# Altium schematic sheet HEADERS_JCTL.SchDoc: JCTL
size A3; Author: Silvio Navaretti; CompanyName: ARDUINO; DrawnBy: Silvio Navaretti; Engineer: Silvio Navaretti; Organization: ARDUINO; SheetNumber: 23; SheetTotal: 51; RevAuthor: Silvio Navaretti
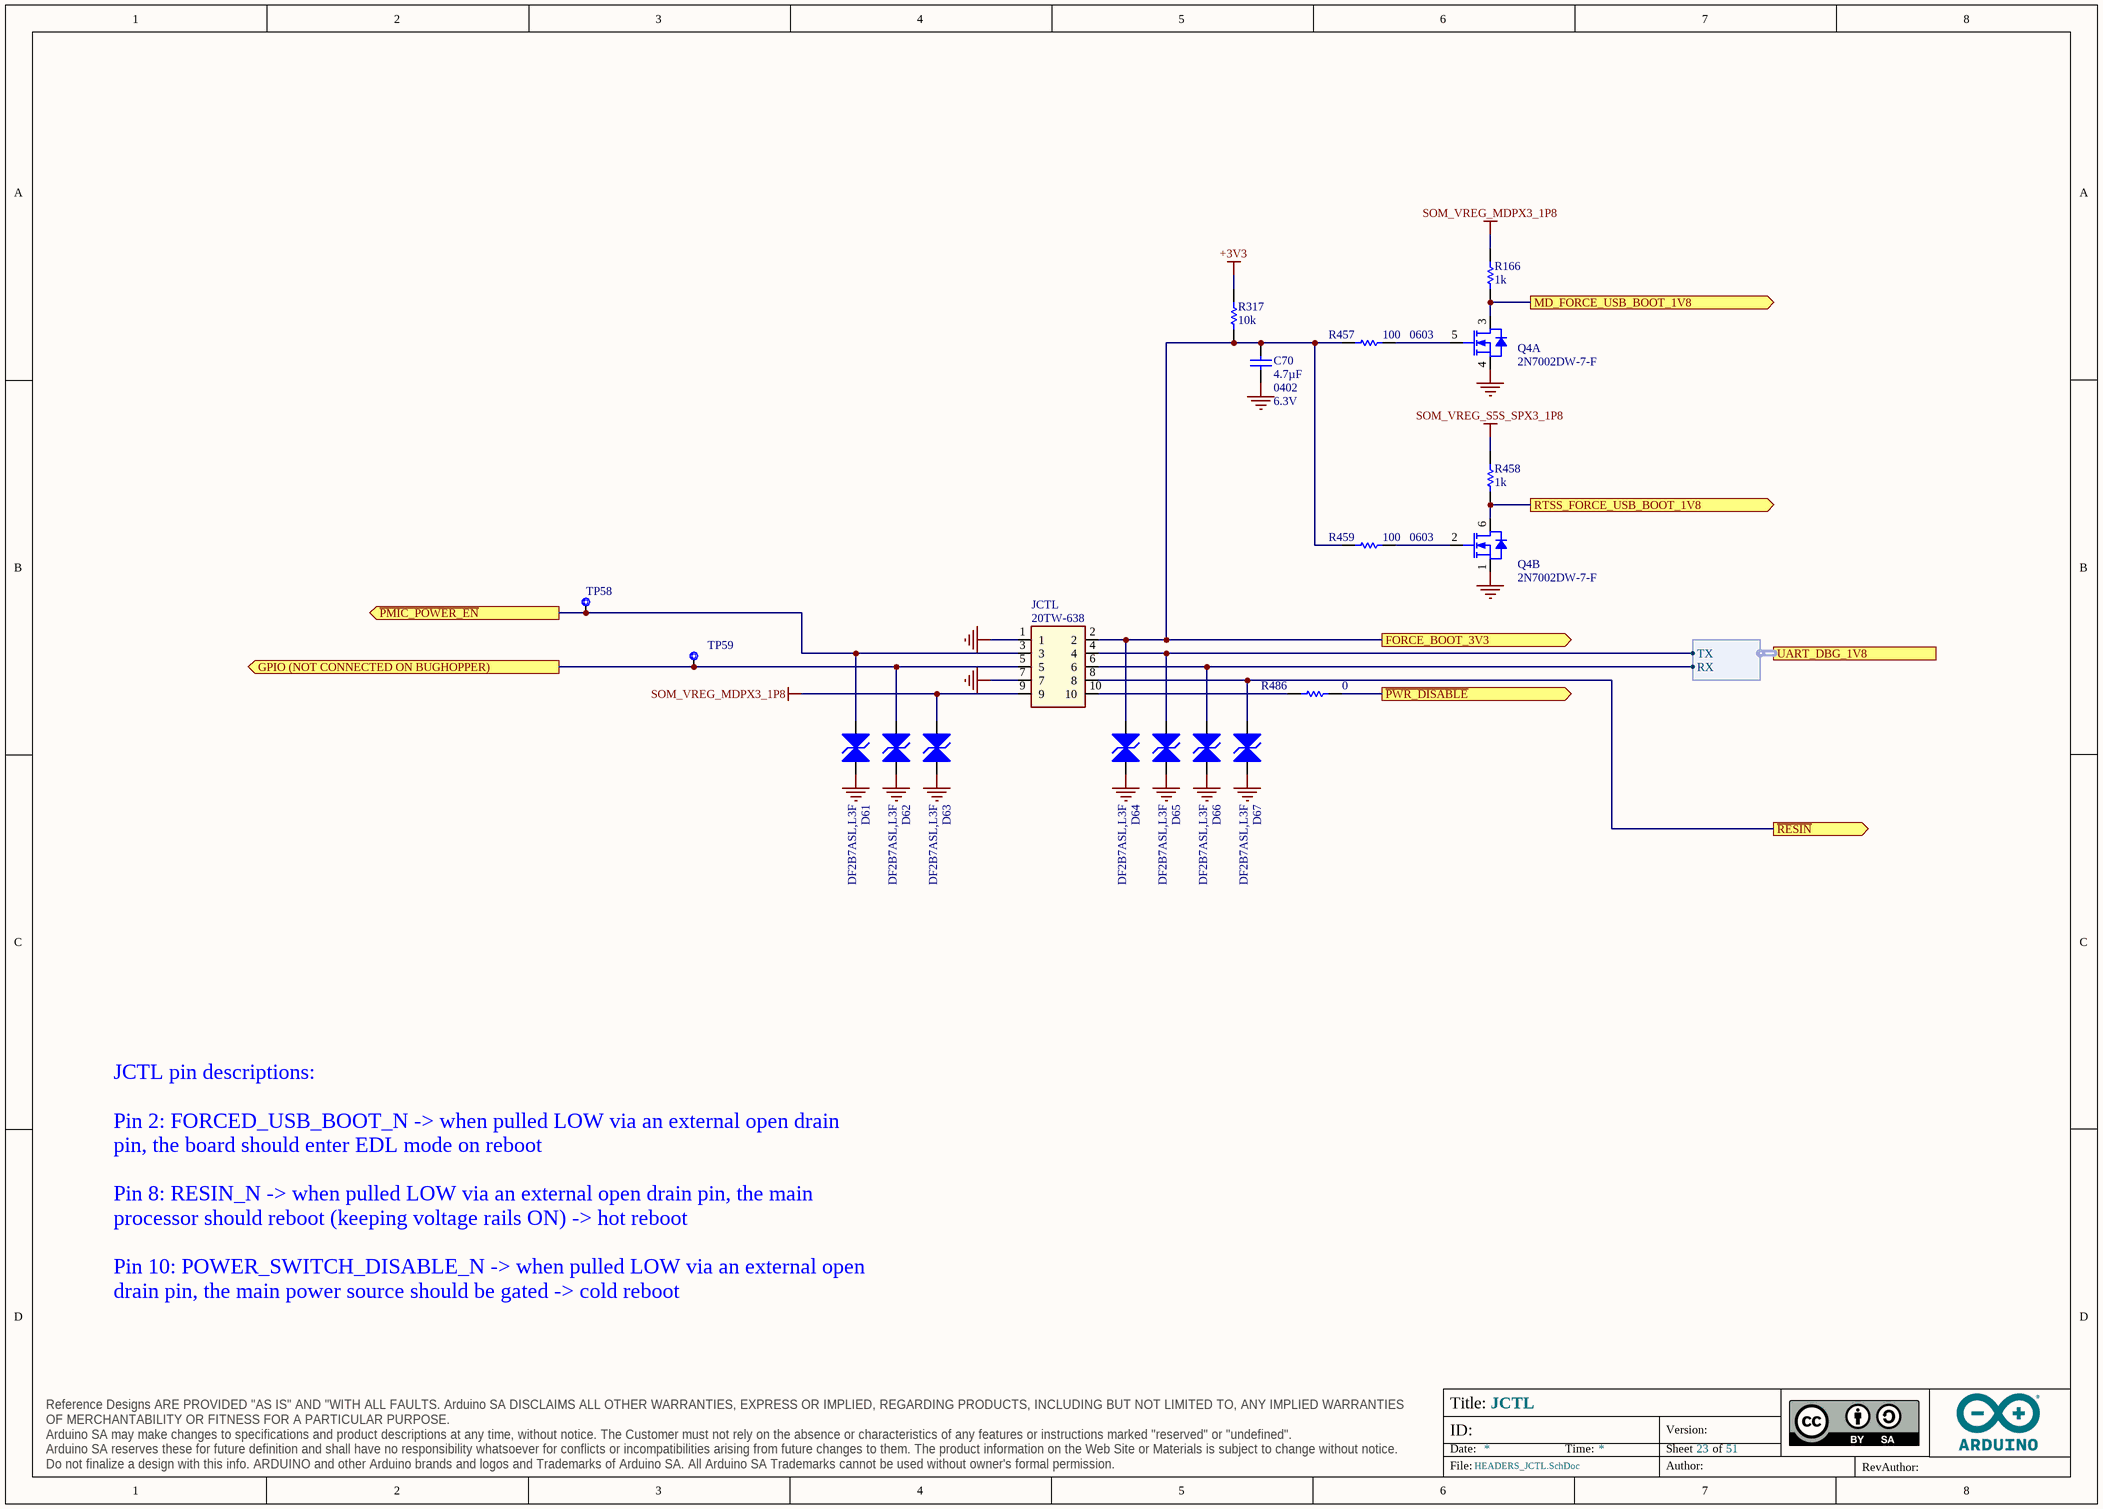
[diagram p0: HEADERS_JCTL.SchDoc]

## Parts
C70  value 4.7µF  Case Code (Imperial): 0402  Voltage: 6.3V  [CAP-0402]  (hidden comment: C1005A475M6R3NT)
D61  DF2B7ASL,L3F  [DF2B7ASL,L3F]
D62  DF2B7ASL,L3F  [DF2B7ASL,L3F]
D63  DF2B7ASL,L3F  [DF2B7ASL,L3F]
D64  DF2B7ASL,L3F  [DF2B7ASL,L3F]
D65  DF2B7ASL,L3F  [DF2B7ASL,L3F]
D66  DF2B7ASL,L3F  [DF2B7ASL,L3F]
D67  DF2B7ASL,L3F  [DF2B7ASL,L3F]
JCTL  20TW-638  [20TW-638]
Q4  2N7002DW-7-F  [SOT363]  (parts A,B of 2)
R166  value 1k  [RES-0201]  (hidden comment: RC0201FR-071KL)
R317  value 10k  [RES-0201]  (hidden comment: RC0201FR-0710KL)
R457  value 100  Case Code (Imperial): 0603  [RES-0603]  (hidden comment: CRCW0603100RFKEAC)
R458  value 1k  [RES-0201]  (hidden comment: RC0201FR-071KL)
R459  value 100  Case Code (Imperial): 0603  [RES-0603]  (hidden comment: CRCW0603100RFKEAC)
R486  value 0  [RES-0201]  (hidden comment: CRCW02010000Z0ED)
TP58  Test point 1.00mm  [TP-1.00MM]  (value not drawn)  (no BOM)
TP59  Test point 1.00mm  [TP-1.00MM]  (value not drawn)  (no BOM)

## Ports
FORCE_BOOT_3V3 (out), GPIO (NOT CONNECTED ON BUGHOPPER) (out), MD_FORCE_USB_BOOT_1V8 (out), RTSS_FORCE_USB_BOOT_1V8 (out), UART_DBG_1V8 (harness UART), ~{PMIC_POWER_EN} (out), ~{PWR_DISABLE} (out), ~{RESIN} (out)

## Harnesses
UART: TX, RX

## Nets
+3V3: R317.2
GND: C70.2 D61.1(A1) D62.1(A1) D63.1(A1) D64.1(A1) D65.1(A1) D66.1(A1) D67.1(A1) JCTL.1 JCTL.7 Q4.1(S) Q4.4(S)
SOM_VREG_MDPX3_1P8: D63.2(A2) JCTL.9 R166.1
SOM_VREG_S5S_SPX3_1P8: R458.1
FORCE_BOOT_3V3: C70.1 D64.2(A2) JCTL.2 R317.1 R457.2 R459.2 ; port FORCE_BOOT_3V3
GPIO (NOT CONNECTED ON BUGHOPPER): D62.2(A2) JCTL.5 TP59.X ; port GPIO (NOT CONNECTED ON BUGHOPPER)
MD_FORCE_USB_BOOT_1V8: Q4.3(D) R166.2 ; port MD_FORCE_USB_BOOT_1V8
~{PMIC_POWER_EN}: D61.2(A2) JCTL.3 TP58.X ; port ~{PMIC_POWER_EN}
~{PWR_DISABLE}: R486.1 ; port ~{PWR_DISABLE}
~{RESIN}: D67.2(A2) JCTL.8 ; port ~{RESIN}
RTSS_FORCE_USB_BOOT_1V8: Q4.6(D) R458.2 ; port RTSS_FORCE_USB_BOOT_1V8
NetD65_2: D65.2(A2) JCTL.4 ; port UART_DBG_1V8.TX
NetD66_2: D66.2(A2) JCTL.6 ; port UART_DBG_1V8.RX
NetJCTL_10: JCTL.10 R486.2
NetQ4_2: Q4.2(G) R459.1
NetQ4_5: Q4.5(G) R457.1

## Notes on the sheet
- JCTL pin descriptions:
  Pin 2: FORCED_USB_BOOT_N -> when pulled LOW via an external open drain pin, the board should enter EDL mode on reboot
  Pin 8: RESIN_N -> when pulled LOW via an external open drain pin, the main processor should reboot (keeping voltage rails ON) -> hot reboot
  Pin 10: POWER_SWITCH_DISABLE_N -> when pulled LOW via an external open drain pin, the main power source should be gated -> cold reboot

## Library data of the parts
C70 = C0037-A.14: CAP CHIP 0402 4.7uF 20% 6V3 X5R; Manufacturer: Hottech; Code Arduino: 0833
D61-D67 = D0099-5: TVS BIDIRECTIONAL SMD Vr 5.5V, Vbr min 5.8V, 0.62x0.32mm; Manufacturer: TOSHIBA; Vforward max: 0V; Ireverse max: 1µA; Power max: 80W; Code Arduino: D0099; Vreverse max: 20V
JCTL = J0570-A.1: CONN HEADER MALE 10POS 2x5 2.54mm SMD; Manufacturer: 4UCONN; Number of Contacts: 10; Connector Type: BOARD CONNECTOR; Code Arduino: J0570
Q4 = T0011-A.12: MOSFET 2N-CH 60V 0.32A SOT363; Manufacturer: Diodes Inc.; Device Type: Mosfet 2N-CH SMD; Code Arduino: A5500
R166 R458 = R0195-A.22: RES CHIP 0201 1k 1% 1/20W; Manufacturer: Yageo; Power: 50mW; Temperature coefficient: 200ppm; Code Arduino: R0195
R317 = R0145-A.21: RES CHIP 0201 10k 1% 1/20W; Manufacturer: Yageo; Power: 50mW; Temperature coefficient: 200ppm; Code Arduino: R0145
R457 R459 = R0105-A.22: RES CHIP 0603 100R 1% 1/10W; Manufacturer: Vishay; Power: 100mW; Temperature coefficient: 100ppm; Code Arduino: A5099
R486 = R0140-A.21: RES CHIP 0201 0R; Manufacturer: Vishay; Temperature coefficient: 0ppm; Code Arduino: R0140; Power: 50mW; Tolerance: 0%
TP58 TP59 = UT0013-A.6: Part Number: This is not a component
